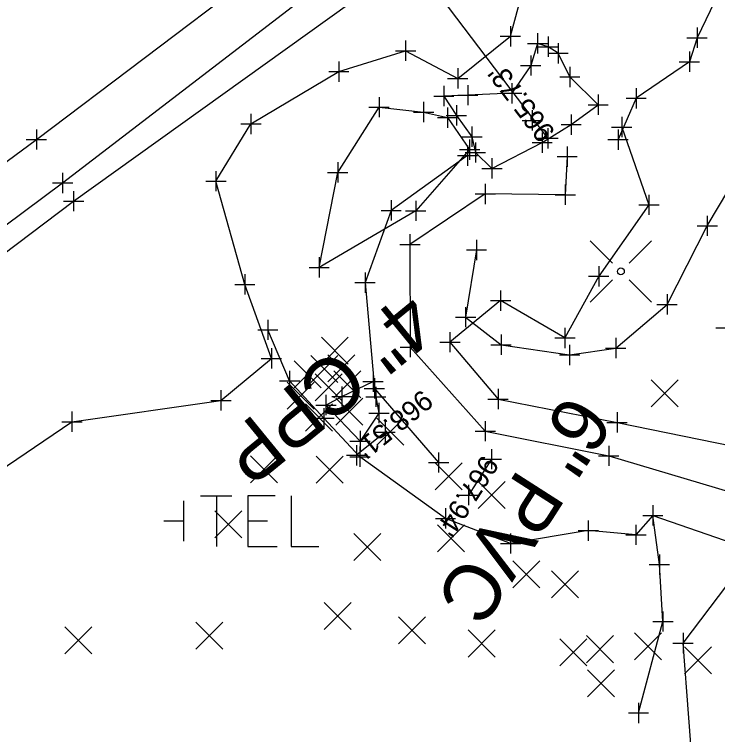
# Model space of a CAD drawing. Extents: x 120332 to 120776, y 463407 to 463745.
# Drawn here: x 120461.49 to 120496.22, y 463500.91 to 463536.5 of the extents above; entities that cross this region are included whole.
import ezdxf

# ---------------------------------------------------------------- set-up
doc = ezdxf.new("R2010")
doc.units = 0
for name, color, linetype in [('DR_X_Erosion_Control', 7, 'Continuous'), ('DR_X_Storm_Sewer', 7, 'Continuous'), ('DR_X_Text', 7, 'Continuous'), ('DV_X_Property_Line', 7, 'Continuous'), ('DV_X_Section_VMS_Line', 7, 'Continuous'), ('GE_X_Alignment', 7, 'Continuous'), ('GE_X_Alignment_100_Bearings', 7, 'Continuous'), ('GE_X_Alignment_100_Cardinal_Points', 7, 'Continuous'), ('GE_X_Alignment_100_Stations', 7, 'Continuous'), ('SC_Scratch1', 7, 'Continuous'), ('SC_Scratch3', 7, 'Continuous'), ('SV_P_Control_Cells_Set', 7, 'Continuous'), ('SV_X_Break_Lines', 7, 'Continuous'), ('SV_X_Mon_Cells_Found', 7, 'Continuous'), ('SV_X_Random_Point', 7, 'Continuous'), ('SV_X_Void_Area', 7, 'Continuous')]:
    doc.layers.add(name, color=color, linetype=linetype)

msp = doc.modelspace()

# ---------------------------------------------------------------- linework, layer by layer
at = {"layer": 'DR_X_Erosion_Control'}
for points in [[(120482.877, 463531.396), (120483.969, 463529.814), (120481.307, 463526.792), (120476.54, 463523.998), (120477.454, 463528.693), (120479.497, 463531.914), (120481.697, 463531.674)], [(120479.337, 463517.602), (120479.493, 463516.801), (120478.557, 463515.416), (120476.877, 463517.194), (120477.662, 463517.617), (120479.201, 463518.353)]]:
    msp.add_lwpolyline(points, close=True, dxfattribs=at)
at = {"layer": 'DR_X_Storm_Sewer'}
for p, q in [((120487.838, 463530.379), (120457.075, 463571.006)), ((120479.797, 463515.862), (120478.389, 463514.711)), ((120485.046, 463514.52), (120483.91, 463512.745))]:
    msp.add_line(p, q, dxfattribs=at)
at = {"layer": 'DV_X_Property_Line'}
for p, q in [((120487.067, 463531.758), (120487.067, 463530.758)), ((120486.567, 463531.258), (120487.567, 463531.258)), ((120487.067, 463531.258), (120487.067, 463531.258)), ((120487.838, 463530.879), (120487.838, 463529.879)), ((120487.338, 463530.379), (120488.338, 463530.379)), ((120487.838, 463530.379), (120487.838, 463530.379)), ((120479.797, 463516.362), (120479.797, 463515.362)), ((120479.297, 463515.862), (120480.297, 463515.862)), ((120479.797, 463515.862), (120479.797, 463515.862)), ((120478.389, 463515.211), (120478.389, 463514.211)), ((120477.889, 463514.711), (120478.889, 463514.711)), ((120478.389, 463514.711), (120478.389, 463514.711)), ((120485.046, 463515.02), (120485.046, 463514.02)), ((120484.546, 463514.52), (120485.546, 463514.52)), ((120485.046, 463514.52), (120485.046, 463514.52)), ((120483.91, 463513.245), (120483.91, 463512.245)), ((120483.41, 463512.745), (120484.41, 463512.745)), ((120483.91, 463512.745), (120483.91, 463512.745))]:
    msp.add_line(p, q, dxfattribs=at)
at = {"layer": 'DV_X_Section_VMS_Line'}
for p, q in [((120489.932, 463525.302), (120491.025, 463524.209)), ((120491.859, 463524.209), (120492.95, 463525.302)), ((120489.932, 463522.284), (120491.025, 463523.377)), ((120491.859, 463523.377), (120492.95, 463522.284))]:
    msp.add_line(p, q, dxfattribs=at)
msp.add_circle((120491.442, 463523.799), 0.17, dxfattribs=at)
at = {"layer": 'GE_X_Alignment'}
msp.add_lwpolyline([(120400.783, 463479.739), (120442.737, 463510.894), (120464.41, 463527.268), (120481.243, 463539.36), (120504.939, 463557.897), (120520.741, 463569.694), (120562.769, 463600.781)], dxfattribs=at)
at = {"layer": 'GE_X_Alignment_100_Bearings'}
msp.add_lwpolyline([(120400.107, 463480.542), (120441.635, 463511.608), (120463.868, 463528.172), (120480.156, 463540.694), (120504.522, 463558.726), (120520.212, 463570.416), (120561.992, 463601.903)], dxfattribs=at)
at = {"layer": 'GE_X_Alignment_100_Cardinal_Points'}
msp.add_lwpolyline([(120399.179, 463482.462), (120440.008, 463513.656), (120462.571, 463530.317), (120478.529, 463542.396), (120503.143, 463560.741), (120518.65, 463572.527), (120560.392, 463604.032)], dxfattribs=at)
at = {"layer": 'GE_X_Alignment_100_Stations'}
msp.add_lwpolyline([(120399.179, 463482.462), (120440.008, 463513.656), (120462.571, 463530.317), (120478.529, 463542.396), (120503.143, 463560.741), (120518.65, 463572.527), (120560.392, 463604.032)], dxfattribs=at)
at = {"layer": 'SC_Scratch3'}
for p, q in [((120469.857, 463510.464), (120469.857, 463512.464)), ((120469.857, 463511.464), (120468.862, 463511.464))]:
    msp.add_line(p, q, dxfattribs=at)
for points in [[(120470.674, 463512.706), (120472.229, 463512.706)], [(120471.461, 463512.706), (120471.461, 463510.206)], [(120474.374, 463512.706), (120473.016, 463512.706), (120473.016, 463510.206), (120474.473, 463510.206)], [(120475.161, 463512.706), (120475.161, 463510.206), (120476.52, 463510.206)], [(120473.016, 463511.466), (120473.981, 463511.466)]]:
    msp.add_lwpolyline(points, dxfattribs=at)
at = {"layer": 'SV_P_Control_Cells_Set'}
for p, q in [((120476.647, 463519.214), (120477.98, 463520.549)), ((120476.647, 463520.549), (120477.98, 463519.214)), ((120476.968, 463518.341), (120478.302, 463519.676)), ((120476.968, 463519.676), (120478.302, 463518.341)), ((120475.303, 463518.039), (120476.636, 463519.374)), ((120475.303, 463519.374), (120476.636, 463518.039)), ((120476.129, 463518.301), (120477.462, 463519.636)), ((120476.129, 463519.636), (120477.462, 463518.301)), ((120476.338, 463517.41), (120477.671, 463518.745)), ((120476.338, 463518.745), (120477.671, 463517.41)), ((120477.272, 463517.548), (120478.605, 463518.883)), ((120477.272, 463518.883), (120478.605, 463517.548)), ((120474.954, 463516.994), (120476.287, 463518.329)), ((120474.954, 463518.329), (120476.287, 463516.994)), ((120492.932, 463517.103), (120494.266, 463518.438)), ((120492.932, 463518.438), (120494.266, 463517.103)), ((120477.356, 463516.205), (120478.69, 463517.54)), ((120477.356, 463517.54), (120478.69, 463516.205)), ((120475.857, 463515.912), (120477.191, 463517.247)), ((120475.857, 463517.247), (120477.191, 463515.912)), ((120479.38, 463515.215), (120480.714, 463516.55)), ((120479.38, 463516.55), (120480.714, 463515.215)), ((120473.145, 463513.358), (120474.478, 463514.693)), ((120473.145, 463514.693), (120474.478, 463513.358)), ((120476.387, 463513.333), (120477.72, 463514.668)), ((120476.387, 463514.668), (120477.72, 463513.333)), ((120482.275, 463512.999), (120483.608, 463514.334)), ((120482.275, 463514.334), (120483.608, 463512.999)), ((120484.392, 463512.083), (120485.725, 463513.418)), ((120484.392, 463513.418), (120485.725, 463512.083)), ((120471.383, 463510.63), (120472.717, 463511.965)), ((120471.383, 463511.965), (120472.717, 463510.63)), ((120482.379, 463509.937), (120483.712, 463511.271)), ((120482.379, 463511.271), (120483.712, 463509.937)), ((120478.251, 463509.521), (120479.584, 463510.856)), ((120478.251, 463510.856), (120479.584, 463509.521)), ((120486.099, 463508.161), (120487.432, 463509.496)), ((120486.099, 463509.496), (120487.432, 463508.161)), ((120488.015, 463507.666), (120489.348, 463509.002)), ((120488.015, 463509.002), (120489.348, 463507.666)), ((120476.788, 463506.107), (120478.122, 463507.442)), ((120476.788, 463507.442), (120478.122, 463506.107)), ((120480.462, 463505.401), (120481.796, 463506.736)), ((120480.462, 463506.736), (120481.796, 463505.401)), ((120463.971, 463504.907), (120465.304, 463506.242)), ((120463.971, 463506.242), (120465.304, 463504.907)), ((120470.443, 463505.128), (120471.777, 463506.463)), ((120470.443, 463506.463), (120471.777, 463505.128)), ((120483.896, 463504.746), (120485.229, 463506.081)), ((120483.896, 463506.081), (120485.229, 463504.746)), ((120489.742, 463504.466), (120491.076, 463505.801)), ((120489.742, 463505.801), (120491.076, 463504.466)), ((120492.12, 463504.606), (120493.454, 463505.941)), ((120492.12, 463505.941), (120493.454, 463504.606)), ((120488.423, 463504.313), (120489.756, 463505.648)), ((120488.423, 463505.648), (120489.756, 463504.313)), ((120494.592, 463503.918), (120495.925, 463505.253)), ((120494.592, 463505.253), (120495.925, 463503.918)), ((120489.788, 463502.78), (120491.122, 463504.115)), ((120489.788, 463504.115), (120491.122, 463502.78))]:
    msp.add_line(p, q, dxfattribs=at)
at = {"layer": 'SV_X_Break_Lines'}
for points in [[(120484.313, 463524.856), (120483.774, 463521.539), (120485.522, 463520.173), (120488.907, 463519.672), (120491.187, 463520.013), (120493.725, 463522.168), (120495.711, 463526.051), (120499.479, 463532.381), (120502.593, 463536.029), (120511.09, 463542.995), (120517.622, 463549.058), (120527.801, 463557.76), (120570.164, 463589.063)], [(120404.479, 463476.085), (120417.279, 463484.282), (120427.882, 463492.664), (120446.763, 463504.904), (120457.39, 463511.512), (120460.212, 463513.576), (120464.328, 463516.37), (120471.69, 463517.424), (120474.179, 463519.501), (120472.867, 463523.159), (120471.441, 463528.255), (120473.169, 463531.082), (120477.51, 463533.672), (120480.807, 463534.7), (120483.381, 463533.337), (120485.988, 463535.413), (120486.753, 463538.233), (120491.559, 463542.13), (120495.696, 463547.265)], [(120491.483, 463530.93), (120492.828, 463527.087), (120490.35, 463523.556), (120488.68, 463520.51), (120485.5, 463522.358), (120482.999, 463520.302), (120485.375, 463517.49), (120491.257, 463516.335), (120498.603, 463514.836), (120508.041, 463515.603), (120517.701, 463510.345), (120521.213, 463507.551), (120532.191, 463505.703), (120540.092, 463504.676), (120541.486, 463506.795)], [(120483.865, 463529.517), (120480.094, 463526.815), (120478.808, 463523.245), (120479.266, 463518.016), (120482.44, 463514.358)], [(120492.315, 463501.98), (120493.52, 463506.499), (120493.347, 463509.314), (120493.021, 463511.745), (120492.186, 463510.781), (120489.832, 463510.991), (120485.993, 463510.354), (120482.779, 463511.596), (120478.552, 463514.64), (120476.775, 463516.541), (120475.08, 463518.39), (120474.002, 463520.911)], [(120493.021, 463511.745), (120507.644, 463506.679), (120516.926, 463499.666), (120527.888, 463499.377), (120537.634, 463500.119)], [(120488.527, 463488.372), (120495.533, 463493.15), (120492.87, 463497.881), (120495.086, 463498.049), (120494.515, 463505.436), (120496.729, 463508.352), (120498.855, 463507.09), (120503.514, 463506.356), (120508.21, 463503.911), (120515.351, 463498.402), (120522.141, 463496.552), (120536.706, 463497.244)]]:
    msp.add_lwpolyline(points, dxfattribs=at)
at = {"layer": 'SV_X_Mon_Cells_Found'}
for p, q in [((120485.988, 463535.913), (120485.988, 463534.913)), ((120495.203, 463535.845), (120495.203, 463534.845)), ((120485.488, 463535.413), (120486.488, 463535.413)), ((120485.988, 463535.413), (120485.988, 463535.413)), ((120487.325, 463535.564), (120487.325, 463534.564)), ((120487.848, 463535.401), (120487.848, 463534.401)), ((120494.703, 463535.345), (120495.703, 463535.345)), ((120495.203, 463535.345), (120495.203, 463535.345)), ((120480.807, 463535.2), (120480.807, 463534.2)), ((120486.825, 463535.064), (120487.825, 463535.064)), ((120487.325, 463535.064), (120487.325, 463535.064)), ((120488.34, 463535.075), (120488.34, 463534.075)), ((120480.307, 463534.7), (120481.307, 463534.7)), ((120480.807, 463534.7), (120480.807, 463534.7)), ((120487.348, 463534.901), (120488.348, 463534.901)), ((120487.848, 463534.901), (120487.848, 463534.901)), ((120494.829, 463534.661), (120494.829, 463533.661)), ((120486.987, 463534.471), (120486.987, 463533.471)), ((120487.84, 463534.575), (120488.84, 463534.575)), ((120488.34, 463534.575), (120488.34, 463534.575)), ((120477.51, 463534.172), (120477.51, 463533.172)), ((120486.487, 463533.971), (120487.487, 463533.971)), ((120486.987, 463533.971), (120486.987, 463533.971)), ((120488.921, 463533.904), (120488.921, 463532.904)), ((120494.329, 463534.161), (120495.329, 463534.161)), ((120494.829, 463534.161), (120494.829, 463534.161)), ((120477.01, 463533.672), (120478.01, 463533.672)), ((120477.51, 463533.672), (120477.51, 463533.672)), ((120483.381, 463533.837), (120483.381, 463532.837)), ((120482.881, 463533.337), (120483.881, 463533.337)), ((120483.381, 463533.337), (120483.381, 463533.337)), ((120488.421, 463533.404), (120489.421, 463533.404)), ((120488.921, 463533.404), (120488.921, 463533.404)), ((120482.698, 463532.963), (120482.698, 463531.963)), ((120483.883, 463533.007), (120483.883, 463532.007)), ((120486.056, 463533.101), (120486.056, 463532.101)), ((120492.198, 463532.852), (120492.198, 463531.852)), ((120483.383, 463532.507), (120484.383, 463532.507)), ((120483.883, 463532.507), (120483.883, 463532.507)), ((120485.556, 463532.601), (120486.556, 463532.601)), ((120486.056, 463532.601), (120486.056, 463532.601)), ((120490.321, 463532.532), (120490.321, 463531.532)), ((120479.497, 463532.414), (120479.497, 463531.414)), ((120481.697, 463532.174), (120481.697, 463531.174)), ((120482.198, 463532.463), (120483.198, 463532.463)), ((120482.698, 463532.463), (120482.698, 463532.463)), ((120491.698, 463532.352), (120492.698, 463532.352)), ((120492.198, 463532.352), (120492.198, 463532.352)), ((120478.997, 463531.914), (120479.997, 463531.914)), ((120479.497, 463531.914), (120479.497, 463531.914)), ((120482.877, 463531.896), (120482.877, 463530.896)), ((120483.315, 463532.009), (120483.315, 463531.009)), ((120489.821, 463532.032), (120490.821, 463532.032)), ((120490.321, 463532.032), (120490.321, 463532.032)), ((120473.169, 463531.582), (120473.169, 463530.582)), ((120481.197, 463531.674), (120482.197, 463531.674)), ((120481.697, 463531.674), (120481.697, 463531.674)), ((120482.815, 463531.509), (120483.815, 463531.509)), ((120483.315, 463531.509), (120483.315, 463531.509)), ((120488.987, 463531.549), (120488.987, 463530.549)), ((120491.483, 463531.43), (120491.483, 463530.43)), ((120472.669, 463531.082), (120473.669, 463531.082)), ((120473.169, 463531.082), (120473.169, 463531.082)), ((120482.377, 463531.396), (120483.377, 463531.396)), ((120482.877, 463531.396), (120482.877, 463531.396)), ((120488.487, 463531.049), (120489.487, 463531.049)), ((120488.987, 463531.049), (120488.987, 463531.049)), ((120462.571, 463530.817), (120462.571, 463529.817)), ((120462.571, 463530.817), (120462.571, 463529.817)), ((120484.083, 463530.951), (120484.083, 463529.951)), ((120490.983, 463530.93), (120491.983, 463530.93)), ((120491.301, 463530.813), (120491.301, 463529.813)), ((120491.483, 463530.93), (120491.483, 463530.93)), ((120483.583, 463530.451), (120484.583, 463530.451)), ((120484.083, 463530.451), (120484.083, 463530.451)), ((120487.554, 463530.662), (120487.554, 463529.662)), ((120462.071, 463530.317), (120463.071, 463530.317)), ((120462.071, 463530.317), (120463.071, 463530.317)), ((120462.571, 463530.317), (120462.571, 463530.317)), ((120462.571, 463530.317), (120462.571, 463530.317)), ((120483.865, 463530.017), (120483.865, 463529.017)), ((120483.969, 463530.314), (120483.969, 463529.314)), ((120484.254, 463530.171), (120484.254, 463529.171)), ((120487.054, 463530.162), (120488.054, 463530.162)), ((120487.554, 463530.162), (120487.554, 463530.162)), ((120490.801, 463530.313), (120491.801, 463530.313)), ((120491.301, 463530.313), (120491.301, 463530.313)), ((120483.469, 463529.814), (120484.469, 463529.814)), ((120483.754, 463529.671), (120484.754, 463529.671)), ((120483.969, 463529.814), (120483.969, 463529.814)), ((120484.254, 463529.671), (120484.254, 463529.671)), ((120488.788, 463529.97), (120488.788, 463528.97)), ((120483.365, 463529.517), (120484.365, 463529.517)), ((120483.865, 463529.517), (120483.865, 463529.517)), ((120485.072, 463529.385), (120485.072, 463528.385)), ((120488.288, 463529.47), (120489.288, 463529.47)), ((120488.788, 463529.47), (120488.788, 463529.47)), ((120477.454, 463529.193), (120477.454, 463528.193)), ((120463.868, 463528.672), (120463.868, 463527.672)), ((120471.441, 463528.755), (120471.441, 463527.755)), ((120476.954, 463528.693), (120477.954, 463528.693)), ((120477.454, 463528.693), (120477.454, 463528.693)), ((120484.572, 463528.885), (120485.572, 463528.885)), ((120485.072, 463528.885), (120485.072, 463528.885)), ((120470.941, 463528.255), (120471.941, 463528.255)), ((120471.441, 463528.255), (120471.441, 463528.255)), ((120463.368, 463528.172), (120464.368, 463528.172)), ((120463.868, 463528.172), (120463.868, 463528.172)), ((120484.743, 463528.128), (120484.743, 463527.128)), ((120488.698, 463528.086), (120488.698, 463527.086)), ((120464.41, 463527.768), (120464.41, 463526.768)), ((120484.243, 463527.628), (120485.243, 463527.628)), ((120484.743, 463527.628), (120484.743, 463527.628)), ((120488.198, 463527.586), (120489.198, 463527.586)), ((120488.698, 463527.586), (120488.698, 463527.586)), ((120492.828, 463527.587), (120492.828, 463526.587)), ((120463.91, 463527.268), (120464.91, 463527.268)), ((120464.41, 463527.268), (120464.41, 463527.268)), ((120480.094, 463527.315), (120480.094, 463526.315)), ((120481.307, 463527.292), (120481.307, 463526.292)), ((120479.594, 463526.815), (120480.594, 463526.815)), ((120480.094, 463526.815), (120480.094, 463526.815)), ((120480.807, 463526.792), (120481.807, 463526.792)), ((120481.307, 463526.792), (120481.307, 463526.792)), ((120492.328, 463527.087), (120493.328, 463527.087)), ((120492.828, 463527.087), (120492.828, 463527.087)), ((120495.711, 463526.551), (120495.711, 463525.551)), ((120495.211, 463526.051), (120496.211, 463526.051)), ((120495.711, 463526.051), (120495.711, 463526.051)), ((120481.024, 463525.633), (120481.024, 463524.633)), ((120484.313, 463525.356), (120484.313, 463524.356)), ((120480.524, 463525.133), (120481.524, 463525.133)), ((120481.024, 463525.133), (120481.024, 463525.133)), ((120483.813, 463524.856), (120484.813, 463524.856)), ((120484.313, 463524.856), (120484.313, 463524.856)), ((120476.54, 463524.498), (120476.54, 463523.498)), ((120476.04, 463523.998), (120477.04, 463523.998)), ((120476.54, 463523.998), (120476.54, 463523.998)), ((120490.35, 463524.056), (120490.35, 463523.056)), ((120472.867, 463523.659), (120472.867, 463522.659)), ((120478.808, 463523.745), (120478.808, 463522.745)), ((120478.308, 463523.245), (120479.308, 463523.245)), ((120478.808, 463523.245), (120478.808, 463523.245)), ((120489.85, 463523.556), (120490.85, 463523.556)), ((120490.35, 463523.556), (120490.35, 463523.556)), ((120472.367, 463523.159), (120473.367, 463523.159)), ((120472.867, 463523.159), (120472.867, 463523.159)), ((120485.5, 463522.858), (120485.5, 463521.858)), ((120493.725, 463522.668), (120493.725, 463521.668)), ((120485, 463522.358), (120486, 463522.358)), ((120485.5, 463522.358), (120485.5, 463522.358)), ((120493.225, 463522.168), (120494.225, 463522.168)), ((120493.725, 463522.168), (120493.725, 463522.168)), ((120483.774, 463522.039), (120483.774, 463521.039)), ((120483.274, 463521.539), (120484.274, 463521.539)), ((120483.774, 463521.539), (120483.774, 463521.539)), ((120474.002, 463521.411), (120474.002, 463520.411)), ((120473.502, 463520.911), (120474.502, 463520.911)), ((120474.002, 463520.911), (120474.002, 463520.911)), ((120482.999, 463520.802), (120482.999, 463519.802)), ((120488.68, 463521.01), (120488.68, 463520.01)), ((120496.133, 463521.003), (120497.133, 463521.003)), ((120481.04, 463520.559), (120481.04, 463519.559)), ((120485.522, 463520.673), (120485.522, 463519.673)), ((120488.18, 463520.51), (120489.18, 463520.51)), ((120488.68, 463520.51), (120488.68, 463520.51)), ((120491.187, 463520.513), (120491.187, 463519.513)), ((120480.54, 463520.059), (120481.54, 463520.059)), ((120481.04, 463520.059), (120481.04, 463520.059)), ((120482.499, 463520.302), (120483.499, 463520.302)), ((120482.999, 463520.302), (120482.999, 463520.302)), ((120485.022, 463520.173), (120486.022, 463520.173)), ((120485.522, 463520.173), (120485.522, 463520.173)), ((120488.907, 463520.172), (120488.907, 463519.172)), ((120490.687, 463520.013), (120491.687, 463520.013)), ((120491.187, 463520.013), (120491.187, 463520.013)), ((120474.179, 463520.001), (120474.179, 463519.001)), ((120488.407, 463519.672), (120489.407, 463519.672)), ((120488.907, 463519.672), (120488.907, 463519.672)), ((120473.679, 463519.501), (120474.679, 463519.501)), ((120474.179, 463519.501), (120474.179, 463519.501)), ((120475.08, 463518.89), (120475.08, 463517.89)), ((120479.201, 463518.853), (120479.201, 463517.853)), ((120474.58, 463518.39), (120475.58, 463518.39)), ((120475.08, 463518.39), (120475.08, 463518.39)), ((120478.701, 463518.353), (120479.701, 463518.353)), ((120479.201, 463518.353), (120479.201, 463518.353)), ((120479.266, 463518.516), (120479.266, 463517.516)), ((120471.69, 463517.924), (120471.69, 463516.924)), ((120477.662, 463518.117), (120477.662, 463517.117)), ((120478.766, 463518.016), (120479.766, 463518.016)), ((120479.266, 463518.016), (120479.266, 463518.016)), ((120479.337, 463518.102), (120479.337, 463517.102)), ((120485.375, 463517.99), (120485.375, 463516.99)), ((120476.877, 463517.694), (120476.877, 463516.694)), ((120477.162, 463517.617), (120478.162, 463517.617)), ((120477.662, 463517.617), (120477.662, 463517.617)), ((120478.837, 463517.602), (120479.837, 463517.602)), ((120479.337, 463517.602), (120479.337, 463517.602)), ((120471.19, 463517.424), (120472.19, 463517.424)), ((120471.69, 463517.424), (120471.69, 463517.424)), ((120476.377, 463517.194), (120477.377, 463517.194)), ((120476.877, 463517.194), (120476.877, 463517.194)), ((120479.493, 463517.301), (120479.493, 463516.301)), ((120484.875, 463517.49), (120485.875, 463517.49)), ((120485.375, 463517.49), (120485.375, 463517.49)), ((120464.328, 463516.87), (120464.328, 463515.87)), ((120476.775, 463517.041), (120476.775, 463516.041)), ((120491.257, 463516.835), (120491.257, 463515.835)), ((120476.275, 463516.541), (120477.275, 463516.541)), ((120476.775, 463516.541), (120476.775, 463516.541)), ((120478.993, 463516.801), (120479.993, 463516.801)), ((120479.493, 463516.801), (120479.493, 463516.801)), ((120463.828, 463516.37), (120464.828, 463516.37)), ((120464.328, 463516.37), (120464.328, 463516.37)), ((120484.744, 463516.404), (120484.744, 463515.404)), ((120490.757, 463516.335), (120491.757, 463516.335)), ((120491.257, 463516.335), (120491.257, 463516.335)), ((120478.557, 463515.916), (120478.557, 463514.916)), ((120484.244, 463515.904), (120485.244, 463515.904)), ((120484.744, 463515.904), (120484.744, 463515.904)), ((120478.057, 463515.416), (120479.057, 463515.416)), ((120478.557, 463515.416), (120478.557, 463515.416)), ((120478.552, 463515.14), (120478.552, 463514.14)), ((120490.842, 463515.186), (120490.842, 463514.186)), ((120482.44, 463514.858), (120482.44, 463513.858)), ((120490.342, 463514.686), (120491.342, 463514.686)), ((120490.842, 463514.686), (120490.842, 463514.686)), ((120478.052, 463514.64), (120479.052, 463514.64)), ((120478.552, 463514.64), (120478.552, 463514.64)), ((120481.94, 463514.358), (120482.94, 463514.358)), ((120482.44, 463514.358), (120482.44, 463514.358)), ((120493.021, 463512.245), (120493.021, 463511.245)), ((120482.779, 463512.096), (120482.779, 463511.096)), ((120482.279, 463511.596), (120483.279, 463511.596)), ((120482.779, 463511.596), (120482.779, 463511.596)), ((120489.832, 463511.491), (120489.832, 463510.491)), ((120492.521, 463511.745), (120493.521, 463511.745)), ((120493.021, 463511.745), (120493.021, 463511.745)), ((120492.186, 463511.281), (120492.186, 463510.281)), ((120485.993, 463510.854), (120485.993, 463509.854)), ((120489.332, 463510.991), (120490.332, 463510.991)), ((120489.832, 463510.991), (120489.832, 463510.991)), ((120491.686, 463510.781), (120492.686, 463510.781)), ((120492.186, 463510.781), (120492.186, 463510.781)), ((120485.493, 463510.354), (120486.493, 463510.354)), ((120485.993, 463510.354), (120485.993, 463510.354)), ((120493.347, 463509.814), (120493.347, 463508.814)), ((120492.847, 463509.314), (120493.847, 463509.314)), ((120493.347, 463509.314), (120493.347, 463509.314)), ((120493.52, 463506.999), (120493.52, 463505.999)), ((120493.02, 463506.499), (120494.02, 463506.499)), ((120493.52, 463506.499), (120493.52, 463506.499)), ((120494.515, 463505.936), (120494.515, 463504.936)), ((120494.015, 463505.436), (120495.015, 463505.436)), ((120494.515, 463505.436), (120494.515, 463505.436)), ((120492.315, 463502.48), (120492.315, 463501.48)), ((120491.815, 463501.98), (120492.815, 463501.98)), ((120492.315, 463501.98), (120492.315, 463501.98))]:
    msp.add_line(p, q, dxfattribs=at)
at = {"layer": 'SV_X_Random_Point'}
for points in [[(120569.138, 463593.998), (120559.049, 463586.735), (120546.371, 463576.844), (120533.287, 463567.164), (120519.767, 463557.283), (120508.017, 463548.989), (120499.859, 463541.228), (120497.713, 463540.742), (120496.273, 463537.579), (120495.203, 463535.345), (120494.829, 463534.161), (120492.198, 463532.352), (120491.301, 463530.313)], [(120488.788, 463529.47), (120488.698, 463527.586), (120484.743, 463527.628), (120481.024, 463525.133), (120481.04, 463520.059), (120484.744, 463515.904), (120490.842, 463514.686), (120497.651, 463512.653), (120507.644, 463506.679), (120517.493, 463507.007), (120528.983, 463502.936), (120532.862, 463501.071), (120540.092, 463504.676)]]:
    msp.add_lwpolyline(points, dxfattribs=at)
at = {"layer": 'SV_X_Void_Area'}
msp.add_lwpolyline([(120486.056, 463532.601), (120483.883, 463532.507), (120482.698, 463532.463), (120483.315, 463531.509), (120484.083, 463530.451), (120484.254, 463529.671), (120485.072, 463528.885), (120487.554, 463530.162), (120488.987, 463531.049), (120490.321, 463532.032), (120488.921, 463533.404), (120488.34, 463534.575), (120487.848, 463534.901), (120487.325, 463535.064), (120486.987, 463533.971)], close=True, dxfattribs=at)

# ---------------------------------------------------------------- texts
at = {"layer": 'DR_X_Text'}
for s, rotation, p in [('4" CPP', 219.2728, (120480.834, 463522.933)), ('6" PVC', 237.3749, (120488.793, 463517.866))]:
    msp.add_text(s, height=2.8, rotation=rotation, dxfattribs=at).set_placement(p)
at = {"layer": 'SC_Scratch1'}
for s, rotation, p in [("965.73'", 127.1331, (120488.237, 463530.68)), ("968.51'", 219.2728, (120481.632, 463518.009)), ("967.94'", 237.3749, (120484.625, 463514.789))]:
    msp.add_text(s, height=1, rotation=rotation, dxfattribs=at).set_placement(p)

doc.saveas('drawing.dxf')
